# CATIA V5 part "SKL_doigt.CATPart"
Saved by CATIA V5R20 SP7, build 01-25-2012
Part number: SKL_doigt
Publications: "Droite.1", "Esquisse.1", "Droite.4"
Bounding box of the stored display mesh (mm): x 0 to 0, y 0 to 0, z 0 to 150
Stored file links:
  F:\IAO_placube\SKL_doigt.CATPart
  F:\IAO_placube\Product1.CATProduct
  F:\IAO_placube\SKL_bati.CATPart
  F:\IAO_placube\SKL_general.CATPart
  F:\IAO_placube\SKL_coulisseau.CATPart
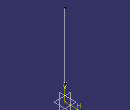
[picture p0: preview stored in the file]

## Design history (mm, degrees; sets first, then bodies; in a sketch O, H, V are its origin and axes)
Set1
  Point1: linked copy from another document
  Line1: linked copy from another document
  Plane1 "plan_ref": linked copy from another document
  DatumCurve1: linked copy from another document
  Point2: linked copy from another document
Body1 (main body)
  Line2: type PtDir, RefPoint Point1, Direction Line1, Start 0, End 20
  Sketch1 on Plane1, origin (0, 0, 0), H (0, 1, 0), V (0, 0, 1)
    point P1 (0, 29.3446)
    reference projected curve E1 from edge of DatumCurve1
    coincidence: P1 V, P1 E1
  Line3: type PtPt, FirstPoint Sketch1, SecondPoint Point2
